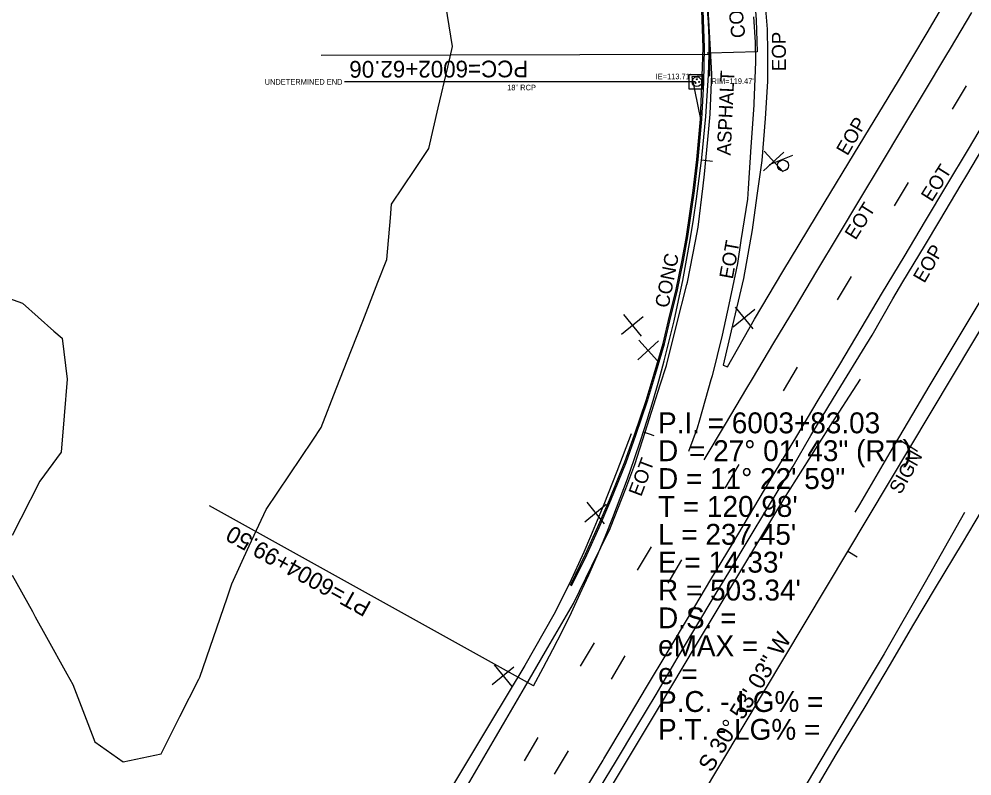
# Model space of a CAD drawing. Extents: x 2132221 to 2141942, y 535736 to 547298.
# Drawn here: x 2138020.6 to 2138362.7, y 540972 to 541243.7 of the extents above; entities that cross this region are included whole.
import ezdxf

# ---------------------------------------------------------------- set-up
doc = ezdxf.new("R2010")
doc.units = 0
for name, color, linetype in [('RD_EX_BldgApp', 7, 'Continuous'), ('RD_EX_BldgApp_txCode', 7, 'Continuous'), ('RD_EX_Conc', 7, 'Continuous'), ('RD_EX_Conc_txCode', 7, 'Continuous'), ('RD_EX_DR_Inlet', 7, 'Continuous'), ('RD_EX_DR_Inlet_txCode', 7, 'Continuous'), ('RD_EX_DR_Pipe', 7, 'Continuous'), ('RD_EX_DR_Pipe_txCode', 7, 'Continuous'), ('RD_EX_GuardRail', 7, 'Continuous'), ('RD_EX_Misc', 7, 'Continuous'), ('RD_EX_Misc_txCode', 7, 'Continuous'), ('RD_EX_Road', 7, 'Continuous'), ('RD_EX_Road_txCode', 7, 'Continuous'), ('RD_EX_VEG', 7, 'Continuous'), ('RD_HC_Cl', 7, 'Continuous'), ('RD_HC_Data', 7, 'Continuous'), ('RD_HC_Data_Tic', 7, 'Continuous')]:
    doc.layers.add(name, color=color, linetype=linetype)

msp = doc.modelspace()

# ---------------------------------------------------------------- linework, layer by layer
at = {"layer": 'RD_EX_BldgApp'}
for p, q in [((2138298.29, 541194.67), (2138289.93, 541191.33)), ((2138336.91, 541092.54), (2138343.13, 541088.64))]:
    msp.add_line(p, q, dxfattribs=at)
msp.add_circle((2138294.84, 541191.11), 2, dxfattribs=at)
at = {"layer": 'RD_EX_Conc'}
for points in [[(2138284.27, 541256), (2138285.23, 541243.42), (2138285.55, 541231.92), (2138268.54, 541231.41), (2138267.68, 541231.37)], [(2138218.51, 541040.53), (2138223.94, 541051.6), (2138228.39, 541061.43), (2138232.52, 541071.16), (2138238.04, 541084.76), (2138241.57, 541094.48), (2138245.73, 541106.79), (2138248.56, 541116.38), (2138251.79, 541127.18), (2138254.1, 541137.03), (2138256.35, 541145.99), (2138258.68, 541157.16), (2138260.24, 541165.67), (2138262.64, 541182.09), (2138263.92, 541193.26), (2138265.26, 541207.78), (2138265.87, 541223.11), (2138266.21, 541233.45), (2138265.75, 541246.72)], [(2138265.87, 541223.11), (2138262.15, 541222.93), (2138265.26, 541207.78)]]:
    msp.add_lwpolyline(points, dxfattribs=at)
at = {"layer": 'RD_EX_DR_Inlet'}
msp.add_line((2138266.03, 541218.63), (2138266.03, 541223.63), dxfattribs=at)
msp.add_lwpolyline([(2138266.03, 541218.63), (2138266.03, 541223.63), (2138261.03, 541223.63), (2138261.03, 541218.63)], close=True, dxfattribs=at)
for centre, radius in [((2138263.94, 541221.15), 1.75), ((2138263.95, 541222.07), 0.175), ((2138264.73, 541221.12), 0.175), ((2138263.39, 541220.77), 0.175)]:
    msp.add_circle(centre, radius, dxfattribs=at)
at = {"layer": 'RD_EX_DR_Pipe'}
msp.add_line((2138263.44, 541221.09), (2138137.48, 541221.09), dxfattribs=at)
at = {"layer": 'RD_EX_GuardRail'}
for points in [[(2138439.29, 541265.65), (2138425.02, 541241.91), (2138410.99, 541218.57), (2138397.65, 541196.1), (2138382.86, 541171.47), (2138369.49, 541148.92), (2138347.62, 541112.4), (2138333.26, 541088.16), (2138322.29, 541069.44), (2138320.66, 541066.74)], [(2138150.12, 540829.23), (2138163.25, 540851.41), (2138179.07, 540877.37), (2138195.37, 540904.74), (2138218.06, 540942.67), (2138231.53, 540965.21), (2138250.22, 540996.35), (2138263.77, 541019.2), (2138277.57, 541042.09), (2138295.19, 541071.38), (2138311.08, 541096.47), (2138322.65, 541114.39)], [(2138240.38, 541094.81), (2138235.25, 541081.3), (2138230.58, 541069.5), (2138225.72, 541057.94), (2138223.3, 541052.38), (2138218.27, 541041.08), (2138212.54, 541029.97), (2138202.18, 541011.64), (2138189.9, 540991.26), (2138177.7, 540970.91), (2138164.93, 540949.47), (2138151.11, 540926.05), (2138139.2, 540905.59), (2138126.35, 540883.58), (2138117.64, 540868.8)], [(2138360.01, 541066.6), (2138345.89, 541041.61), (2138331.18, 541015.84), (2138318.31, 540994.36), (2138303.59, 540969.56), (2138291.83, 540949.88), (2138282.46, 540933.94), (2138269.59, 540912.1), (2138251.26, 540881.23), (2138240.69, 540863.63), (2138223.13, 540834.13), (2138208.73, 540810.18), (2138190.26, 540779.65)]]:
    msp.add_lwpolyline(points, dxfattribs=at)
at = {"layer": 'RD_EX_Misc'}
for p, q in [((2138268.6, 541223.17), (2138268.54, 541231.41)), ((2138355.7, 541211.35), (2138360.69, 541219.74)), ((2138287.86, 541189.16), (2138295.2, 541195.95)), ((2138288.14, 541196.23), (2138294.92, 541188.88)), ((2138334.93, 541176.6), (2138339.93, 541184.99)), ((2138314.47, 541142.87), (2138319.46, 541151.25)), ((2138276.99, 541133.24), (2138284.76, 541139.53)), ((2138277.73, 541140.27), (2138284.03, 541132.5)), ((2138236.86, 541130.59), (2138244.63, 541136.88)), ((2138237.6, 541137.62), (2138243.89, 541129.85)), ((2138242.77, 541121.35), (2138250.12, 541128.13)), ((2138243.05, 541128.41), (2138249.83, 541121.06)), ((2138295.09, 541110.29), (2138300.08, 541118.68)), ((2138274.13, 541075.37), (2138279.13, 541083.76)), ((2138223.66, 541063.28), (2138231.43, 541069.57)), ((2138224.4, 541070.31), (2138230.69, 541062.54)), ((2138242.64, 541045.84), (2138247.64, 541054.23)), ((2138253.6, 541041.17), (2138258.59, 541049.56)), ((2138222.14, 541011.44), (2138227.14, 541019.83)), ((2138233.23, 541006.75), (2138238.22, 541015.14)), ((2138190.45, 541004.89), (2138198.22, 541011.19)), ((2138191.19, 541011.93), (2138197.48, 541004.15)), ((2138202.01, 540977.4), (2138207, 540985.79)), ((2138212.82, 540972.68), (2138217.81, 540981.06))]:
    msp.add_line(p, q, dxfattribs=at)
for points in [[(2138176.59, 540959.95), (2138184.13, 540972.92), (2138191.67, 540985.88), (2138194.49, 540990.74), (2138202.03, 541003.7), (2138209.57, 541016.67), (2138217.11, 541029.64), (2138219.6, 541033.92), (2138226.2, 541047.39), (2138232.79, 541060.86), (2138232.97, 541061.24), (2138238.39, 541075.22), (2138241.7, 541083.76), (2138246.25, 541098.05), (2138250.8, 541112.34), (2138253, 541119.28), (2138256.68, 541133.82), (2138260.35, 541148.36), (2138260.58, 541149.26), (2138263.42, 541163.98), (2138264.37, 541168.94), (2138266.2, 541183.83), (2138266.71, 541187.98), (2138268.11, 541202.92), (2138268.73, 541209.51), (2138269.28, 541223.96), (2138268.46, 541238.94), (2138267.65, 541253.92)], [(2138266.5, 541085.43), (2138274.18, 541098.31), (2138281.86, 541111.2), (2138283.88, 541114.59), (2138291.6, 541127.45), (2138299.31, 541140.32), (2138307.03, 541153.18), (2138314.74, 541166.05), (2138322.46, 541178.91), (2138330.17, 541191.77), (2138337.89, 541204.64), (2138345.6, 541217.5), (2138353.32, 541230.37), (2138354.94, 541233.08), (2138362.64, 541245.96)], [(2138284.29, 541244.51), (2138284.92, 541235.38), (2138284.98, 541228.32), (2138284.35, 541213.33), (2138284.33, 541212.75), (2138283.32, 541197.78), (2138282.32, 541182.81), (2138282.06, 541179.02), (2138279.76, 541164.2), (2138278.47, 541155.9), (2138275.38, 541141.23), (2138273.06, 541130.22), (2138269.37, 541115.68), (2138268.99, 541114.18), (2138264.83, 541099.77), (2138263.99, 541096.87), (2138260.98, 541088.47)], [(2138222.52, 540964.86), (2138230.24, 540977.73), (2138230.49, 540978.16), (2138238.2, 540991.03), (2138245.9, 541003.9), (2138253.6, 541016.77), (2138261.3, 541029.64), (2138269, 541042.52), (2138276.7, 541055.39), (2138284.4, 541068.26), (2138292.1, 541081.13), (2138299.8, 541094.01), (2138307.5, 541106.88), (2138315.21, 541119.75), (2138322.91, 541132.62), (2138330.61, 541145.49), (2138338.31, 541158.37), (2138346.01, 541171.24), (2138353.71, 541184.11), (2138361.41, 541196.98), (2138369.11, 541209.86)]]:
    msp.add_lwpolyline(points, dxfattribs=at)
at = {"layer": 'RD_EX_Road'}
for points in [[(2138288.03, 541254.55), (2138289.17, 541240.06), (2138289.26, 541231.63), (2138289.29, 541221.25), (2138288.46, 541207.99), (2138287.26, 541192.87), (2138285.5, 541180.37), (2138283.83, 541168.01), (2138280.64, 541150.54), (2138276.26, 541131.79), (2138273.42, 541119.51), (2138274.93, 541118.82), (2138284.57, 541135.93), (2138294.83, 541153.11), (2138309.61, 541177.65), (2138320.57, 541195.48), (2138336.28, 541221.47), (2138346.62, 541238.77), (2138351.88, 541247.72)], [(2138218.95, 541040.31), (2138224.4, 541051.38), (2138228.85, 541061.23), (2138232.99, 541070.97), (2138238.51, 541084.58), (2138242.04, 541094.32), (2138246.21, 541106.64), (2138249.04, 541116.23), (2138252.28, 541127.05), (2138254.59, 541136.91), (2138256.83, 541145.88), (2138259.17, 541157.07), (2138260.73, 541165.59), (2138263.14, 541182.03), (2138264.42, 541193.21), (2138265.76, 541207.74), (2138266.39, 541220.93), (2138266.72, 541233.46), (2138266.25, 541246.75)], [(2138229.32, 540968.13), (2138234.7, 540976.98), (2138242.44, 540989.82), (2138249.3, 541001.21), (2138256.9, 541014.14), (2138263.17, 541024.81), (2138270.92, 541037.66), (2138275.37, 541045.02), (2138283.1, 541057.87), (2138288.68, 541067.14), (2138296.51, 541079.93), (2138298.51, 541083.18), (2138304.88, 541094.19), (2138312.67, 541107.01), (2138315.62, 541111.86), (2138323.45, 541124.65), (2138326.85, 541130.21), (2138334.34, 541143.2), (2138337.89, 541149.35), (2138345.63, 541162.2), (2138351.15, 541171.37), (2138358.83, 541184.26), (2138360.87, 541187.69), (2138368.57, 541200.56)], [(2138191.84, 540778.88), (2138197.03, 540787.77), (2138198.96, 540790.66), (2138200.43, 540790.21), (2138204.63, 540795.14), (2138209.28, 540801.6), (2138215.48, 540812.45), (2138224.52, 540828.09), (2138234.22, 540845.03), (2138237.25, 540850.73), (2138237.83, 540852.61), (2138241.45, 540858.17), (2138248.73, 540870.1), (2138262.65, 540893.61), (2138286.18, 540933.66), (2138291.62, 540941.77), (2138300.91, 540957.55), (2138313.98, 540979.77), (2138324.34, 540996.85), (2138333.47, 541012.15), (2138341.42, 541025.86), (2138349.64, 541039.54), (2138359.33, 541055.59), (2138368.45, 541070.89)]]:
    msp.add_lwpolyline(points, dxfattribs=at)
at = {"layer": 'RD_EX_VEG'}
for points in [[(2138018.13, 541044.12), (2138025.39, 541031), (2138026.41, 541029.16), (2138030.45, 541021.85), (2138037.71, 541008.72), (2138039.87, 541004.83), (2138045.25, 540990.83), (2138047.77, 540984.26), (2138057.92, 540977.05), (2138071.61, 540980), (2138078.37, 540993.4), (2138085.13, 541006.79), (2138085.5, 541007.53), (2138090.38, 541021.71), (2138095.26, 541035.9), (2138096.99, 541040.93), (2138103.25, 541054.56), (2138109.27, 541067.65), (2138117.64, 541080.1), (2138126.01, 541092.55), (2138129.04, 541097.05), (2138134.5, 541111.01), (2138139.97, 541124.98), (2138143.99, 541135.26), (2138149.46, 541149.23), (2138152.63, 541157.33), (2138153.92, 541172.27), (2138154.34, 541177.2), (2138162.66, 541189.68), (2138167.7, 541197.24), (2138171.11, 541211.84), (2138174.52, 541226.45), (2138176.25, 541233.85), (2138173.81, 541248.65)], [(2138009.57, 541146.01), (2138021.87, 541141.66), (2138033.09, 541131.7), (2138036.02, 541129.1), (2138037.89, 541114.4), (2138036.82, 541101.31), (2138035.76, 541088.21), (2138028.01, 541077.79), (2138021.23, 541064.41), (2138018.13, 541058.28)]]:
    msp.add_lwpolyline(points, dxfattribs=at)
at = {"layer": 'RD_HC_Cl'}
msp.add_line((2139719.79, 543396.28), (2136851.48, 538600.7), dxfattribs=at)
for centre, radius, start, end in [((2138047.52, 541230.39), 220.87, 0.1424, 95.1276), ((2138047.44, 541231.33), 219.93, 95.1276, 190.1127), ((2137765.38, 541249.03), 503.34, 330.9109, 357.9396), ((2138948.08, 540422.28), 795.18, 129.53037, 144.22397)]:
    msp.add_arc(centre, radius, start, end, dxfattribs=at)
at = {"layer": 'RD_HC_Data'}
for p, q in [((2138268.4, 541230.94), (2138129, 541230.59)), ((2138205.23, 541004.32), (2138088.93, 541069.03))]:
    msp.add_line(p, q, dxfattribs=at)
at = {"layer": 'RD_HC_Data_Tic'}
for p, q in [((2138265.6, 541193.11), (2138269.58, 541192.66)), ((2138244.73, 541095.48), (2138248.54, 541094.26)), ((2138318.08, 541052.74), (2138321.51, 541050.68))]:
    msp.add_line(p, q, dxfattribs=at)

# ---------------------------------------------------------------- texts
at = {"layer": 'RD_EX_BldgApp_txCode'}
msp.add_text('SIGN', height=5, rotation=60.4283, dxfattribs=at).set_placement((2138337.05, 541072.76))
at = {"layer": 'RD_EX_Conc_txCode'}
for s, rotation, p in [('CONCRETE', 95.8919, (2138281.38, 541237.11)), ('CONC', 78.8969, (2138253.73, 541139.75))]:
    msp.add_text(s, height=5, rotation=rotation, dxfattribs=at).set_placement(p)
at = {"layer": 'RD_EX_DR_Inlet_txCode'}
for s, p in [('UNDETERMINED END', (2138108.78, 541220.1)), ("IE=113.71'", (2138249.15, 541222.09)), ("RIM=119.47'", (2138269.19, 541220.38))]:
    msp.add_text(s, height=2, dxfattribs=at).set_placement(p)
at = {"layer": 'RD_EX_DR_Pipe_txCode'}
msp.add_text('18" RCP', height=2, dxfattribs=at).set_placement((2138195.85, 541218.09))
at = {"layer": 'RD_EX_Misc_txCode'}
for rotation, p in [(57.7697, (2138348.28, 541177.77)), (57.7697, (2138320.9, 541164.1)), (79.6439, (2138276.83, 541150.13)), (69.4357, (2138243.92, 541072.02))]:
    msp.add_text('EOT', height=5, rotation=rotation, dxfattribs=at).set_placement(p)
at = {"layer": 'RD_EX_Road_txCode'}
for s, rotation, p in [('EOP', 90.1987, (2138295.9, 541224.98)), ('ASPHALT', 87.3827, (2138276.07, 541194.61)), ('EOP', 59.7475, (2138317.99, 541194.34)), ('EOP', 59.7475, (2138345.59, 541148.61))]:
    msp.add_text(s, height=5, rotation=rotation, dxfattribs=at).set_placement(p)
at = {"layer": 'RD_HC_Data'}
for s, rotation, p in [('PCC=6002+62.06', 180.1424, (2138203.4, 541228.78)), ('PT=6004+99.50', 150.9109, (2138147.46, 541034.18)), ('S 30%%d 53\' 03" W', 59.1157, (2138269.22, 540973))]:
    msp.add_text(s, height=6, rotation=rotation, dxfattribs=at).set_placement(p)
for s, p in [('P.I. = 6003+83.03', (2138250, 541095)), ('D', (2138250, 541085)), ('    = 27%%d 01\' 43" (RT)', (2138250, 541085)), ('D = 11%%d 22\' 59"', (2138250, 541075)), ("T = 120.98'", (2138250, 541065)), ("L = 237.45'", (2138250, 541055)), ("E = 14.33'", (2138250, 541045)), ("R = 503.34'", (2138250, 541035)), ('D.S. = ', (2138250, 541025)), ('eMAX = ', (2138250, 541015)), ('e = ', (2138250, 541005)), ('P.C. - LG% = ', (2138250, 540995)), ('P.T. - LG% = ', (2138250, 540985))]:
    msp.add_text(s, height=7.5, dxfattribs=at).set_placement(p)

doc.saveas('drawing.dxf')
